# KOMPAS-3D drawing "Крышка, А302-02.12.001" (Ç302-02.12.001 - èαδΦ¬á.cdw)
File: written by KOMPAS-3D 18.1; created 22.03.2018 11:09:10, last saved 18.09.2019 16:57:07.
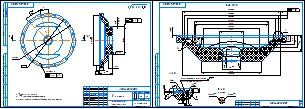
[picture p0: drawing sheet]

Sheets 1-2: A3, landscape

Document properties: Автор: Милов; Масса: 2.64473; Параметр неуказанной шероховатости: Ra 3,2; Форматы листов документа: 2xA3; Полное имя файла: ..\3Д ПВХ\А302-01.12.001 - Крышка.m3d; Организация: Милов

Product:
- Part/product: Крышка  | designation А302-02.12.001
    Материал: Поливинилхлорид (density 1350 kg/m3)
    Масса: 2.64473
    Раздел спецификации: Детали
    Форматы листов документа: 2xA3
    Примечание: @100~)2xA3
    source file: ..\3Д ПВХ\А302-02.00.000 - ASTRA-302 (МЭ200)\А302-02.12.001 - Крышка.cdw, А302-02.12.001 - Крышка.cdw
- Part/product: Крышка  | designation А302-01.12.001
    Материал: Поливинилхлорид (density 1350 kg/m3)
    Масса: 2.45398
    Раздел спецификации: Детали
    Форматы листов документа: 2xA3
    Примечание: @100~)2xA3
    source file: ..\3Д ПВХ\А302-01.12.001 - Крышка.cdw
- Part/product: Крышка  | designation А302-03.12.001
    Материал: Поливинилхлорид (density 1350 kg/m3)
    Масса: 2.71786
    Раздел спецификации: Детали
    Форматы листов документа: 2xA3
    Примечание: @100~)2xA3
    source file: ..\Чертежи Полипропилен\А302-03.12.001 - Крышка.cdw

Title block, sheet 1: Наименование: Крышка; designation: А302-02.12.001; Материал: Поливинилхлорид / Стержень  300; Масса: 2,64; scale: 1:2; sheet number: 1; Количество листов документа: 2; organisation: АО «Астерион»; Форматы листов документа: A3; stored path: Z:\Мембранные насосы\Мембранный электропривод\А302-00.00.000 - ASTRA-302 (МЭ200)\Чертежи\А302-00.12.001 - Крышка.cdw; Разработал: Лифлянд; Проверил: Борисенко; Т. контр.: Лучихин; Утвердил: Григорьева
Title block, sheet 2: Масса: 2,69; sheet number: 2

Views: Вид 1, Вид:4, Проекционный вид 2, Местный разрез 1, Разрез А-А, Выносной элемент 4, Выносной элемент 5, Разрез В-В, Выносной элемент А, Выносной элемент, Выносной элемент Б, Вид:1, Вид:2, Вид:3
Referenced files in Z:\Мембранные насосы\Мембранный электропривод\А302-00.00.000 - ASTRA-302 (МЭ200)\3Д\: А302-00.12.001 - Крышка.m3d
Referenced files in D:\Мембранные насосы\Мембранный электропривод\А302-00.00.000 - ASTRA-302 (МЭ200)\3Д ПВХ\: А302-01.12.001 - Крышка.m3d
Referenced files in \\192.168.87.28\Konstructor_doc\Мембранные насосы\Мембранный электропривод\А302-00.00.000 - ASTRA-302 (МЭ200)\3Д ПВХ\: А302-01.12.001 - Крышка.m3d
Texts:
  Ra 1,6
  Зона контакта с мембраной
  поверхность глянцевая
  Ra 3,2
  Ra 3,2 ( )
Dimensions and other numbers on the sheet: 302; 287; 12 отв.; 6,5; 280; 154; 72; 21,5; 3; 2 фаски; 0,1; 19; 270±0,4; 16,95; 24,53; 244±0,2; 206; 202; 155,43; 6; 0,5; 258±0,3; 33; 44; 0,8; 64,6; 42,6; 164; 8; 20; 50; 1±0,1; 2; 12,5; 12; 2 места; 1:2; 2,64; 2,69

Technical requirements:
  *Размеры для справок.
  ** Обеспечить инструментом.
  Общие допуски ГОСТ 30893.2-mK (H14, h14,  t2/2).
